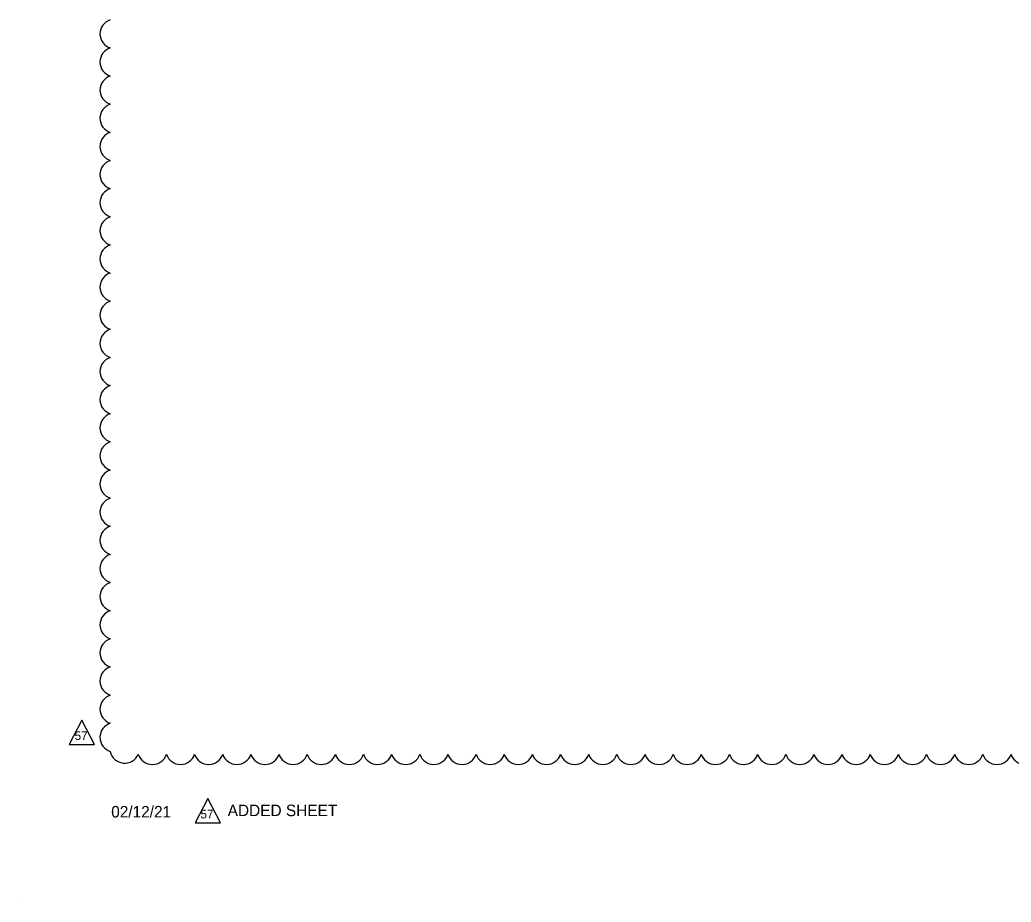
# Model space of a CAD drawing. Extents: x -811 to -790, y -2284 to -2178.
# Drawn here: x -811.34 to -805.31, y -2199.5 to -2194.13 of the extents above; entities that cross this region are included whole.
import ezdxf

# ---------------------------------------------------------------- set-up
doc = ezdxf.new("R2010")
doc.units = 0
for name, color, linetype in [('SheetBorder_dp', 7, 'Continuous'), ('TextMisc', 7, 'Continuous'), ('TextTitle', 7, 'Continuous')]:
    doc.layers.add(name, color=color, linetype=linetype)

msp = doc.modelspace()

# ---------------------------------------------------------------- linework, layer by layer
at = {"layer": 'SheetBorder_dp'}
msp.add_line((-811.3358, -2199.5006), (-811.3358, -2199.5006), dxfattribs=at)
at = {"layer": 'TextMisc'}
for points in [[(-810.9581, -2198.3928), (-811.0351, -2198.5411), (-810.8811, -2198.5411)], [(-810.1928, -2198.8692), (-810.2698, -2199.0175), (-810.1158, -2199.0175)]]:
    msp.add_lwpolyline(points, close=True, dxfattribs=at)
at = {"layer": 'TextTitle'}
for centre, radius, start, end in [((-810.7588, -2194.2199), 0.0897, 107.5, 252.5), ((-810.7588, -2194.391), 0.0897, 107.5, 252.5), ((-810.7588, -2194.5621), 0.0897, 107.5, 252.5), ((-810.7588, -2194.7332), 0.0897, 107.5, 252.5), ((-810.7588, -2194.9044), 0.0897, 107.5, 252.5), ((-810.7588, -2195.0755), 0.0897, 107.5, 252.5), ((-810.7588, -2195.2466), 0.0897, 107.5, 252.5), ((-810.7588, -2195.4177), 0.0897, 107.5, 252.5), ((-810.7588, -2195.5889), 0.0897, 107.5, 252.5), ((-810.7588, -2195.76), 0.0897, 107.5, 252.5), ((-810.7588, -2195.9311), 0.0897, 107.5, 252.5), ((-810.7588, -2196.1022), 0.0897, 107.5, 252.5), ((-810.7588, -2196.2733), 0.0897, 107.5, 252.5), ((-810.7588, -2196.4445), 0.0897, 107.5, 252.5), ((-810.7588, -2196.6156), 0.0897, 107.5, 252.5), ((-810.7588, -2196.7867), 0.0897, 107.5, 252.5), ((-810.7588, -2196.9578), 0.0897, 107.5, 252.5), ((-810.7588, -2197.129), 0.0897, 107.5, 252.5), ((-810.7588, -2197.3001), 0.0897, 107.5, 252.5), ((-810.7588, -2197.4712), 0.0897, 107.5, 252.5), ((-810.7588, -2197.6423), 0.0897, 107.5, 252.5), ((-810.7588, -2197.8134), 0.0897, 107.5, 252.5), ((-810.7588, -2197.9846), 0.0897, 107.5, 252.5), ((-810.7588, -2198.1557), 0.0897, 107.5, 252.5), ((-810.7588, -2198.3268), 0.0897, 107.5, 252.5), ((-810.7588, -2198.4979), 0.0897, 107.5, 252.5), ((-810.698, -2198.5653), 0.0896, 191.74536, 336.74536), ((-810.5301, -2198.5737), 0.0897, 197.5, 342.5), ((-810.359, -2198.5737), 0.0897, 197.5, 342.5), ((-810.1879, -2198.5737), 0.0897, 197.5, 342.5), ((-810.0167, -2198.5737), 0.0897, 197.5, 342.5), ((-809.8456, -2198.5737), 0.0897, 197.5, 342.5), ((-809.6745, -2198.5737), 0.0897, 197.5, 342.5), ((-809.5034, -2198.5737), 0.0897, 197.5, 342.5), ((-809.3323, -2198.5737), 0.0897, 197.5, 342.5), ((-809.1611, -2198.5737), 0.0897, 197.5, 342.5), ((-808.99, -2198.5737), 0.0897, 197.5, 342.5), ((-808.8189, -2198.5737), 0.0897, 197.5, 342.5), ((-808.6478, -2198.5737), 0.0897, 197.5, 342.5), ((-808.4766, -2198.5737), 0.0897, 197.5, 342.5), ((-808.3055, -2198.5737), 0.0897, 197.5, 342.5), ((-808.1344, -2198.5737), 0.0897, 197.5, 342.5), ((-807.9633, -2198.5737), 0.0897, 197.5, 342.5), ((-807.7921, -2198.5737), 0.0897, 197.5, 342.5), ((-807.621, -2198.5737), 0.0897, 197.5, 342.5), ((-807.4499, -2198.5737), 0.0897, 197.5, 342.5), ((-807.2788, -2198.5737), 0.0897, 197.5, 342.5), ((-807.1077, -2198.5737), 0.0897, 197.5, 342.5), ((-806.9365, -2198.5737), 0.0897, 197.5, 342.5), ((-806.7654, -2198.5737), 0.0897, 197.5, 342.5), ((-806.5943, -2198.5737), 0.0897, 197.5, 342.5), ((-806.4232, -2198.5737), 0.0897, 197.5, 342.5), ((-806.252, -2198.5737), 0.0897, 197.5, 342.5), ((-806.0809, -2198.5737), 0.0897, 197.5, 342.5), ((-805.9098, -2198.5737), 0.0897, 197.5, 342.5), ((-805.7387, -2198.5737), 0.0897, 197.5, 342.5), ((-805.5676, -2198.5737), 0.0897, 197.5, 342.5), ((-805.3964, -2198.5737), 0.0897, 197.5, 342.5), ((-805.2253, -2198.5737), 0.0897, 197.5, 342.5)]:
    msp.add_arc(centre, radius, start, end, dxfattribs=at)

# ---------------------------------------------------------------- texts
at = {"layer": 'TextMisc'}
for p in [(-811.0024, -2198.5147), (-810.2372, -2198.9912)]:
    msp.add_text('57', height=0.0525, rotation=360, dxfattribs=at).set_placement(p)
at = {"layer": 'TextTitle'}
for s, p in [('02/12/21', (-810.7803, -2198.9855)), ('ADDED SHEET', (-810.0721, -2198.9774))]:
    msp.add_text(s, height=0.07, rotation=0, dxfattribs=at).set_placement(p)

doc.saveas('drawing.dxf')
